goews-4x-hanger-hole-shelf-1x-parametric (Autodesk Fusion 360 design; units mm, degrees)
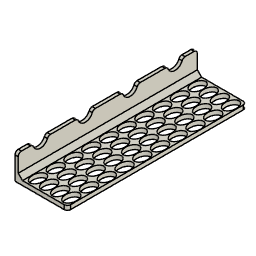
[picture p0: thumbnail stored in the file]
parameter "HoleWidth" = 15
parameter "HoleDepth" = 10
base_feature "Base Feature" bodies "Quad Plate Blank"
work_plane "WorkPlane1" AlongDistance 4
delete_face "DeleteFace1"
sketch "Sketch1" plane through (0, 0, -108.1504) normal (0, 0, 1) x axis (-1, 0, 0)
  line L1 (-103.15, 20.8) -> (-103.15, -146.8)
  line L2 (-142.15, 20.8) -> (-103.15, 20.8)
  line L3 (-145.15, -143.8) -> (-145.15, 17.8)
  line L4 (-103.15, -146.8) -> (-142.15, -146.8)
  line L5 (-134.75, 19.2) -> (-144.75, 19.2)
  line L6 (-134.75, 4.2) -> (-134.75, 19.2)
  line L7 (-144.75, 4.2) -> (-134.75, 4.2)
  line L8 (-144.75, 19.2) -> (-144.75, 4.2)
  line L9 (-142.15, 20.8) -> (-103.15, 20.8)
  line L10 (-145.15, -143.8) -> (-145.15, 17.8)
  line L11 (-103.15, -146.8) -> (-142.15, -146.8)
  line L12 (-103.15, 20.8) -> (-103.15, -146.8)
  line L13 (-144.75, 19.2) -> (-134.75, 4.2)
  line L14 (-134.75, 19.2) -> (-144.75, 4.2)
  curve K1 (-139.75, 4.2) -> (-139.75, 19.2)
  curve K2 (-134.75, 11.7) -> (-144.75, 11.7)
  arc A1 centre (-142.15, 17.8) radius 3 clockwise from (-145.15, 17.8) to (-142.15, 20.8)
  arc A2 centre (-142.15, -143.8) radius 3 clockwise from (-142.15, -146.8) to (-145.15, -143.8)
  arc A3 centre (-142.15, -143.8) radius 3 clockwise from (-142.15, -146.8) to (-145.15, -143.8)
  arc A4 centre (-142.15, 17.8) radius 3 clockwise from (-145.15, 17.8) to (-142.15, 20.8)
  closed curve K3 centre (-139.75, 11.7)
  closed curve K4 centre (-139.75, -4.9)
  closed curve K5 centre (-139.75, -21.5)
  closed curve K6 centre (-139.75, -38.1)
  closed curve K7 centre (-129.35, 11.7)
  closed curve K8 centre (-129.35, -4.9)
  closed curve K9 centre (-129.35, -21.5)
  closed curve K10 centre (-129.35, -38.1)
  closed curve K11 centre (-139.75, -54.7)
  closed curve K12 centre (-129.35, -54.7)
  closed curve K13 centre (-139.75, -71.3)
  closed curve K14 centre (-129.35, -71.3)
  closed curve K15 centre (-139.75, -87.9)
  closed curve K16 centre (-129.35, -87.9)
  closed curve K17 centre (-139.75, -104.5)
  closed curve K18 centre (-129.35, -104.5)
  closed curve K19 centre (-139.75, -121.1)
  closed curve K20 centre (-129.35, -121.1)
  closed curve K21 centre (-139.75, -137.7)
  closed curve K22 centre (-129.35, -137.7)
  closed curve K23 centre (-118.95, 11.7)
  closed curve K24 centre (-108.55, 11.7)
  closed curve K25 centre (-118.95, -4.9)
  closed curve K26 centre (-108.55, -4.9)
  closed curve K27 centre (-118.95, -21.5)
  closed curve K28 centre (-108.55, -21.5)
  closed curve K29 centre (-118.95, -38.1)
  closed curve K30 centre (-108.55, -38.1)
  closed curve K31 centre (-118.95, -54.7)
  closed curve K32 centre (-108.55, -54.7)
  closed curve K33 centre (-118.95, -71.3)
  closed curve K34 centre (-108.55, -71.3)
  closed curve K35 centre (-118.95, -87.9)
  closed curve K36 centre (-108.55, -87.9)
  closed curve K37 centre (-118.95, -104.5)
  closed curve K38 centre (-108.55, -104.5)
  closed curve K39 centre (-118.95, -121.1)
  closed curve K40 centre (-108.55, -121.1)
  closed curve K41 centre (-118.95, -137.7)
  closed curve K42 centre (-108.55, -137.7)
  point P3 (-103.15, 20.8)
  point P14 (-103.15, 20.8)
  point P15 (-145.15, 20.8)
  point P24 (-139.75, 19.2)
  point P25 (-139.75, 4.2)
  point P26 (-144.75, 11.7)
  point P27 (-134.75, 11.7)
  point P23 (-139.75, 11.7)
  point P4 (-142.15, 20.8)
  point P8 (-142.15, -146.8)
  point P10 (-144.75, 19.2)
  point P11 (-134.75, 19.2)
  point P13 (-144.75, 4.2)
  point P16 (-103.15, -146.8)
  horizontal L5
  vertical L6
  horizontal L7
  vertical L8
  horizontal L9
  vertical L10
  horizontal L11
  vertical L12
  coincident P3 P14
  tangent L11 A3
  tangent L10 A3
  coincident P15 L9
  coincident P15 L10
  tangent L9 A4
  tangent L10 A4
  coincident K3 P24
  coincident K3 P25
  coincident K3 P26
  coincident K3 P27
  midpoint L13 P23
  perpendicular L7 K1
  coincident L8 P26
  coincident L7 P25
  dimension "d10" distance P4 P8 = 167.6
  dimension "d11" distance P10 P11 = 10 (= "HoleDepth")
  dimension "d12" distance P10 P13 = 15 (= "HoleWidth")
  dimension "d13" distance L2 L5 = 1.6 (= "( 167.6 mm - ( HoleWidth * QTYHolesWide ) ) / ( QTYHolesWide + 1 )")
  dimension "d18" distance L3 L8 = 0.4 (= "( 42 mm - ( HoleDepth * QTYHolesDeep ) ) / ( QTYHolesDeep + 1 )")
  dimension "d26" distance P14 P15 = 42
  dimension "d27" distance P14 P16 = 167.6
  dimension "d28" radius A3 = 3
  dimension "d29" radius A4 = 3
  dimension "d16" R-Pattern1-uDistance = 10.4 (= "HoleDepth + ( 42 mm - ( HoleDepth * QTYHolesDeep ) ) / ( QTYHolesDeep + 1 )")
  dimension "d17" value = -16.6 (= "R-Pattern1-vDistance")
extrude "Extrude4" add sketch "Sketch1" profile of L1 L2 A1 L3 A2 L4 L9 L10 L11 L12 A3 A4 K3 K4 K5 K6 K7 K8 K9 K10 K11 K12 K13 K14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 against normal blind 4
named bodies: "Quad Plate Blank"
